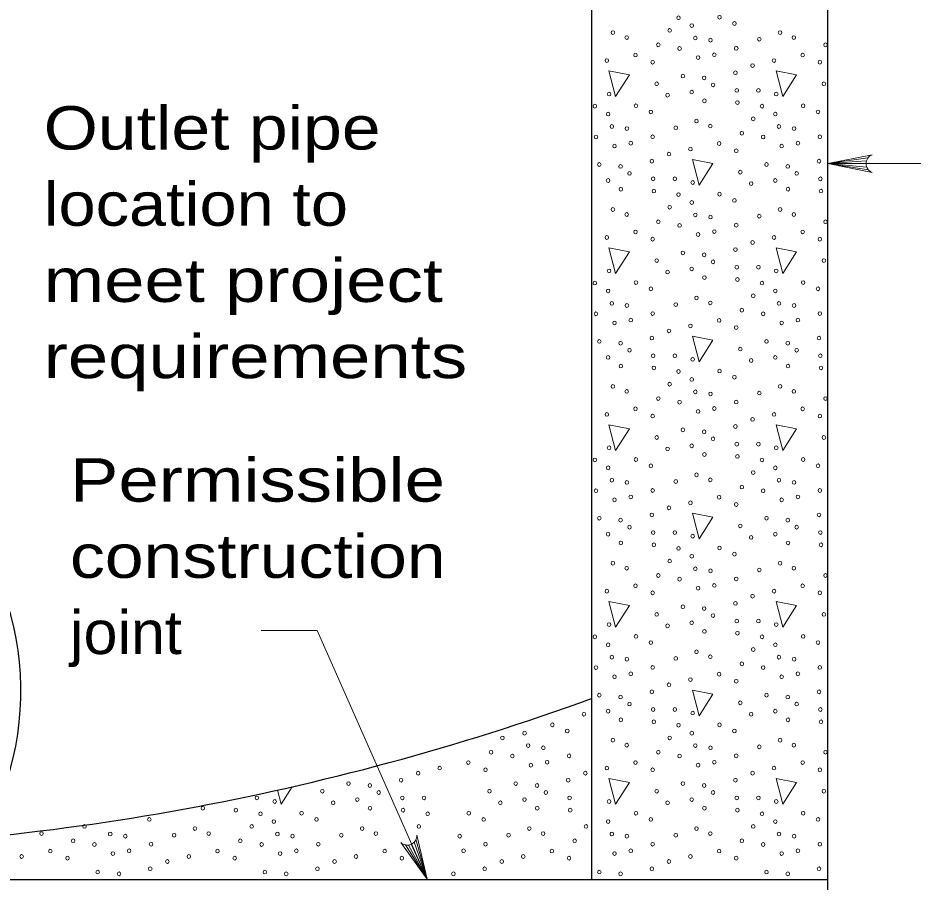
# Model space of a CAD drawing. Extents: x 1352.5 to 1386.5, y 735.9 to 779.9.
# Drawn here: x 1364.306 to 1367.523, y 771.328 to 774.436 of the extents above; entities that cross this region are included whole.
import ezdxf

# ---------------------------------------------------------------- set-up
doc = ezdxf.new("R2010")
doc.units = 0
doc.header["$LTSCALE"] = 0.062
doc.layers.add('1', color=7, linetype='Continuous', lineweight=13)

msp = doc.modelspace()

# ---------------------------------------------------------------- linework, layer by layer
at = {"layer": '1'}
for p, q in [((1367.36042, 773.93233), (1367.21625, 773.91217)), ((1367.35558, 773.92233), (1367.21625, 773.91217)), ((1367.35408, 773.91217), (1367.21625, 773.91217)), ((1367.35658, 773.89917), (1367.21625, 773.91217)), ((1367.36217, 773.88983), (1367.21625, 773.91217)), ((1368.51183, 773.91217), (1367.21625, 773.91217)), ((1365.25217, 771.60883), (1365.29175, 771.67117)), ((1365.23892, 771.659), (1365.25217, 771.60883)), ((1365.73008, 771.47242), (1365.77625, 771.33917)), ((1365.73633, 771.48125), (1365.77625, 771.33917)), ((1365.69833, 771.46217), (1365.77625, 771.33917)), ((1365.70942, 771.46183), (1365.77625, 771.33917)), ((1365.71933, 771.46475), (1365.77625, 771.33917))]:
    msp.add_line(p, q, dxfattribs=at)
at = {"layer": '1', "lineweight": 25}
msp.add_line((1367.21625, 771.33708), (1359.56983, 771.33708), dxfattribs=at)
for points in [[(1366.579, 775.15983), (1366.40908, 775.15983), (1366.36658, 775.11483), (1366.36658, 771.33708)], [(1358.38042, 774.73258), (1359.56983, 774.73258), (1359.56983, 770.66242), (1367.21625, 770.66242), (1367.21625, 774.73258), (1368.40567, 774.73258), (1369.78625, 774.73258)]]:
    msp.add_lwpolyline(points, dxfattribs=at)
at = {"layer": '1'}
for points in [[(1366.42942, 774.24517), (1366.45367, 774.15292), (1366.50308, 774.23083)], [(1367.03017, 774.24517), (1367.05442, 774.15292), (1367.10392, 774.23083)], [(1366.72975, 773.92717), (1366.754, 773.835), (1366.8035, 773.91275)], [(1366.42942, 773.60908), (1366.45367, 773.51692), (1366.50308, 773.59475)], [(1367.03017, 773.60908), (1367.05442, 773.51692), (1367.10392, 773.59475)], [(1366.72975, 773.29108), (1366.754, 773.199), (1366.8035, 773.27675)], [(1366.42942, 772.97308), (1366.45367, 772.88092), (1366.50308, 772.95875)], [(1367.03017, 772.97308), (1367.05442, 772.88092), (1367.10392, 772.95875)], [(1366.72975, 772.65508), (1366.754, 772.56292), (1366.8035, 772.64067)], [(1366.42942, 772.337), (1366.45367, 772.24492), (1366.50308, 772.32275)], [(1367.03017, 772.337), (1367.05442, 772.24492), (1367.10392, 772.32275)], [(1366.72975, 772.01908), (1366.754, 771.92692), (1366.8035, 772.00467)], [(1366.42942, 771.701), (1366.45367, 771.60883), (1366.50308, 771.68667)], [(1367.03017, 771.701), (1367.05442, 771.60883), (1367.10392, 771.68667)]]:
    msp.add_lwpolyline(points, close=True, dxfattribs=at)
for points in [[(1367.3755, 773.88025), (1367.21625, 773.91217), (1367.3755, 773.944)], [(1365.77625, 771.33917), (1365.38183, 772.23358), (1365.18017, 772.23358)], [(1365.7395, 771.49742), (1365.77625, 771.33917), (1365.6815, 771.47108)]]:
    msp.add_lwpolyline(points, dxfattribs=at)
for centre, start, end in [((1367.38838, 773.91218), 112.08782, 247.91395), ((1365.70517, 771.49596), 226.44643, 2.27256)]:
    msp.add_arc(centre, 0.03438, start, end, dxfattribs=at)
for centre in [(1366.67956, 774.43659), (1366.82715, 774.43829), (1366.72737, 774.40824), (1366.88067, 774.41598), (1366.44407, 774.38306), (1366.49353, 774.36504), (1366.64787, 774.39106), (1366.74039, 774.36361), (1366.97018, 774.35905), (1367.04482, 774.38306), (1367.09429, 774.36504), (1366.60707, 774.33928), (1366.79471, 774.35582), (1367.20783, 774.33928), (1366.52512, 774.30234), (1366.68357, 774.32582), (1366.80847, 774.3035), (1366.88717, 774.32661), (1367.12588, 774.30234), (1366.42214, 774.28257), (1366.5868, 774.27658), (1366.75005, 774.29317), (1366.9458, 774.26455), (1367.0229, 774.28257), (1367.18755, 774.27658), (1366.88422, 774.23879), (1366.60141, 774.1993), (1366.69548, 774.22681), (1366.77203, 774.22018), (1367.20217, 774.1993), (1366.72712, 774.16925), (1366.80392, 774.19501), (1366.88908, 774.17524), (1366.96697, 774.17524), (1366.43025, 774.16236), (1366.64036, 774.15807), (1366.77283, 774.13803), (1367.03101, 774.16236), (1366.37918, 774.11858), (1366.52677, 774.12027), (1366.89148, 774.13146), (1366.97994, 774.11858), (1367.12753, 774.12027), (1366.42699, 774.09022), (1366.58029, 774.09796), (1366.94825, 774.07305), (1367.02775, 774.09022), (1367.18104, 774.09796), (1366.44001, 774.04559), (1366.49433, 774.0378), (1366.6698, 774.04104), (1366.74444, 774.06505), (1366.79391, 774.04703), (1367.04077, 774.04559), (1367.09509, 774.0378), (1366.38319, 774.0078), (1366.5868, 774.0086), (1366.90745, 774.02127), (1366.98395, 774.0078), (1367.18755, 774.0086), (1366.44967, 773.97515), (1366.5081, 773.98549), (1366.8255, 773.98432), (1367.05043, 773.97515), (1367.10885, 773.98549), (1366.64542, 773.94653), (1366.72252, 773.96455), (1366.88717, 773.95856), (1366.3951, 773.90879), (1366.58384, 773.92077), (1366.99586, 773.90879), (1367.1846, 773.92077), (1366.47165, 773.90217), (1366.50354, 773.87699), (1366.90179, 773.88129), (1367.07241, 773.90217), (1367.1043, 773.87699), (1366.42674, 773.85123), (1366.5887, 773.85722), (1366.6666, 773.85722), (1367.0275, 773.85123), (1367.18946, 773.85722), (1366.47245, 773.82002), (1366.5911, 773.81344), (1366.73063, 773.84434), (1366.94074, 773.84005), (1367.07321, 773.82002), (1367.19186, 773.81344), (1366.67956, 773.80056), (1366.82715, 773.80226), (1366.64787, 773.75503), (1366.72737, 773.77221), (1366.88067, 773.77995), (1366.44407, 773.74703), (1366.49353, 773.72901), (1366.74039, 773.72758), (1366.79471, 773.71979), (1366.97018, 773.72302), (1367.04482, 773.74703), (1367.09429, 773.72901), (1366.60707, 773.70325), (1366.68357, 773.68979), (1366.88717, 773.69058), (1367.20783, 773.70325), (1366.52512, 773.66631), (1366.75005, 773.65714), (1366.80847, 773.66747), (1367.12588, 773.66631), (1366.42214, 773.64654), (1366.5868, 773.64055), (1366.9458, 773.62852), (1367.0229, 773.64654), (1367.18755, 773.64055), (1366.69548, 773.59078), (1366.88422, 773.60276), (1366.60141, 773.56327), (1366.77203, 773.58415), (1366.80392, 773.55898), (1367.20217, 773.56327), (1366.43025, 773.52633), (1366.72712, 773.53322), (1366.88908, 773.53921), (1366.96697, 773.53921), (1367.03101, 773.52633), (1366.64036, 773.52204), (1366.77283, 773.502), (1366.89148, 773.49543), (1366.37918, 773.48255), (1366.52677, 773.48424), (1366.58029, 773.46193), (1366.97994, 773.48255), (1367.12753, 773.48424), (1367.18104, 773.46193), (1366.42699, 773.45419), (1366.74444, 773.42902), (1366.94825, 773.43702), (1367.02775, 773.45419), (1366.44001, 773.40956), (1366.49433, 773.40177), (1366.6698, 773.40501), (1366.79391, 773.411), (1367.04077, 773.40956), (1367.09509, 773.40177), (1366.38319, 773.37177), (1366.5868, 773.37257), (1366.90745, 773.38524), (1366.98395, 773.37177), (1367.18755, 773.37257), (1366.44967, 773.33912), (1366.5081, 773.34946), (1366.8255, 773.34829), (1367.05043, 773.33912), (1367.10885, 773.34946), (1366.64542, 773.3105), (1366.72252, 773.32852), (1366.88717, 773.32253), (1366.3951, 773.27277), (1366.47165, 773.26614), (1366.58384, 773.28474), (1366.99586, 773.27277), (1367.07241, 773.26614), (1367.1846, 773.28474), (1366.50354, 773.24096), (1366.90179, 773.24526), (1367.1043, 773.24096), (1366.42674, 773.2152), (1366.5887, 773.22119), (1366.6666, 773.22119), (1366.73063, 773.20831), (1366.94074, 773.20402), (1367.0275, 773.2152), (1367.18946, 773.22119), (1366.47245, 773.18399), (1366.5911, 773.17741), (1367.07321, 773.18399), (1367.19186, 773.17741), (1366.67956, 773.16453), (1366.82715, 773.16623), (1366.88067, 773.14392), (1366.44407, 773.111), (1366.64787, 773.119), (1366.72737, 773.13618), (1367.04482, 773.111), (1366.49353, 773.09298), (1366.74039, 773.09155), (1366.79471, 773.08376), (1366.97018, 773.08699), (1367.09429, 773.09298), (1366.60707, 773.06722), (1366.68357, 773.05376), (1366.88717, 773.05455), (1367.20783, 773.06722), (1366.42214, 773.01051), (1366.52512, 773.03028), (1366.75005, 773.02111), (1366.80847, 773.03144), (1367.0229, 773.01051), (1367.12588, 773.03028), (1366.5868, 773.00452), (1366.9458, 772.99249), (1367.18755, 773.00452), (1366.69548, 772.95475), (1366.77203, 772.94812), (1366.88422, 772.96673), (1366.60141, 772.92724), (1366.80392, 772.92295), (1367.20217, 772.92724), (1366.43025, 772.8903), (1366.64036, 772.88601), (1366.72712, 772.89719), (1366.88908, 772.90318), (1366.96697, 772.90318), (1367.03101, 772.8903), (1366.52677, 772.84822), (1366.77283, 772.86597), (1366.89148, 772.8594), (1367.12753, 772.84822), (1366.37918, 772.84652), (1366.42699, 772.81816), (1366.58029, 772.8259), (1366.97994, 772.84652), (1367.02775, 772.81816), (1367.18104, 772.8259), (1366.74444, 772.79299), (1366.94825, 772.80099), (1366.44001, 772.77353), (1366.49433, 772.76574), (1366.6698, 772.76898), (1366.79391, 772.77497), (1367.04077, 772.77353), (1367.09509, 772.76574), (1366.38319, 772.73574), (1366.5868, 772.73654), (1366.90745, 772.74921), (1366.98395, 772.73574), (1367.18755, 772.73654), (1366.44967, 772.70309), (1366.5081, 772.71343), (1366.72252, 772.69249), (1366.8255, 772.71226), (1366.88717, 772.6865), (1367.05043, 772.70309), (1367.10885, 772.71343), (1366.64542, 772.67447), (1366.3951, 772.63674), (1366.47165, 772.63011), (1366.58384, 772.64871), (1366.99586, 772.63674), (1367.07241, 772.63011), (1367.1846, 772.64871), (1366.50354, 772.60493), (1366.90179, 772.60923), (1367.1043, 772.60493), (1366.42674, 772.57917), (1366.5887, 772.58516), (1366.6666, 772.58516), (1366.73063, 772.57228), (1366.94074, 772.56799), (1367.0275, 772.57917), (1367.18946, 772.58516), (1366.47245, 772.54796), (1366.5911, 772.54138), (1366.67956, 772.5285), (1366.82715, 772.5302), (1367.07321, 772.54796), (1367.19186, 772.54138), (1366.72737, 772.50015), (1366.88067, 772.50789), (1366.44407, 772.47497), (1366.64787, 772.48298), (1367.04482, 772.47497), (1366.49353, 772.45695), (1366.60707, 772.43119), (1366.74039, 772.45552), (1366.79471, 772.44773), (1366.97018, 772.45096), (1367.09429, 772.45695), (1367.20783, 772.43119), (1366.68357, 772.41773), (1366.88717, 772.41852), (1366.42214, 772.37448), (1366.52512, 772.39425), (1366.5868, 772.36849), (1366.75005, 772.38508), (1366.80847, 772.39542), (1367.0229, 772.37448), (1367.12588, 772.39425), (1367.18755, 772.36849), (1366.9458, 772.35646), (1366.69548, 772.31872), (1366.77203, 772.3121), (1366.88422, 772.3307), (1366.60141, 772.29121), (1366.80392, 772.28692), (1367.20217, 772.29121), (1366.43025, 772.25427), (1366.64036, 772.24998), (1366.72712, 772.26116), (1366.88908, 772.26715), (1366.96697, 772.26715), (1367.03101, 772.25427), (1366.37918, 772.21049), (1366.52677, 772.21219), (1366.77283, 772.22994), (1366.89148, 772.22337), (1366.97994, 772.21049), (1367.12753, 772.21219), (1366.42699, 772.18213), (1366.58029, 772.18987), (1367.02775, 772.18213), (1367.18104, 772.18987), (1366.74444, 772.15696), (1366.94825, 772.16496), (1366.44001, 772.13751), (1366.49433, 772.12971), (1366.6698, 772.13295), (1366.79391, 772.13894), (1366.90745, 772.11318), (1367.04077, 772.13751), (1367.09509, 772.12971), (1366.38319, 772.09971), (1366.5081, 772.0774), (1366.5868, 772.10051), (1366.8255, 772.07623), (1366.98395, 772.09971), (1367.10885, 772.0774), (1367.18755, 772.10051), (1366.44967, 772.06706), (1366.72252, 772.05646), (1366.88717, 772.05048), (1367.05043, 772.06706), (1366.58384, 772.01268), (1366.64542, 772.03844), (1367.1846, 772.01268), (1366.3951, 772.00071), (1366.47165, 771.99408), (1366.99586, 772.00071), (1367.07241, 771.99408), (1366.50354, 771.9689), (1366.5887, 771.94913), (1366.6666, 771.94913), (1366.90179, 771.9732), (1367.1043, 771.9689), (1367.18946, 771.94913), (1366.33998, 771.93196), (1366.42674, 771.94315), (1366.73063, 771.93625), (1366.94074, 771.93196), (1367.0275, 771.94315), (1366.22639, 771.89417), (1366.47245, 771.91193), (1366.5911, 771.90535), (1366.67956, 771.89247), (1366.82715, 771.89417), (1367.07321, 771.91193), (1367.19186, 771.90535), (1366.12661, 771.86412), (1366.27991, 771.87186), (1366.72737, 771.86412), (1366.88067, 771.87186), (1366.04711, 771.84695), (1366.13963, 771.81949), (1366.44407, 771.83894), (1366.49353, 771.82092), (1366.64787, 771.84695), (1366.74039, 771.81949), (1367.04482, 771.83894), (1367.09429, 771.82092), (1366.00631, 771.79516), (1366.19395, 771.8117), (1366.60707, 771.79516), (1366.79471, 771.8117), (1366.97018, 771.81493), (1367.20783, 771.79516), (1365.92436, 771.75822), (1366.08281, 771.7817), (1366.20772, 771.75939), (1366.28642, 771.78249), (1366.52512, 771.75822), (1366.68357, 771.7817), (1366.80847, 771.75939), (1366.88717, 771.78249), (1367.12588, 771.75822), (1365.82138, 771.73845), (1365.98604, 771.73246), (1366.14929, 771.74905), (1366.42214, 771.73845), (1366.5868, 771.73246), (1366.75005, 771.74905), (1367.0229, 771.73845), (1367.18755, 771.73246), (1365.6827, 771.69467), (1365.74428, 771.72043), (1366.28346, 771.69467), (1366.34504, 771.72043), (1366.88422, 771.69467), (1366.9458, 771.72043), (1365.49397, 771.68269), (1365.57051, 771.67607), (1366.09472, 771.68269), (1366.17127, 771.67607), (1366.69548, 771.68269), (1366.77203, 771.67607), (1365.1647, 771.63112), (1365.3999, 771.65518), (1365.52561, 771.62513), (1365.6024, 771.65089), (1365.68756, 771.63112), (1365.76546, 771.63112), (1366.00066, 771.65518), (1366.12636, 771.62513), (1366.20316, 771.65089), (1366.28832, 771.63112), (1366.60141, 771.65518), (1366.72712, 771.62513), (1366.80392, 771.65089), (1366.88908, 771.63112), (1366.96697, 771.63112), (1367.20217, 771.65518), (1364.97056, 771.59391), (1365.22873, 771.61824), (1365.43885, 771.61395), (1365.57131, 771.59391), (1366.0396, 771.61395), (1366.17207, 771.59391), (1366.43025, 771.61824), (1366.64036, 771.61395), (1366.77283, 771.59391), (1367.03101, 771.61824), (1365.08921, 771.58734), (1365.17767, 771.57446), (1365.32525, 771.57616), (1365.68996, 771.58734), (1365.77843, 771.57446), (1365.92601, 771.57616), (1366.29072, 771.58734), (1366.52677, 771.57616), (1366.89148, 771.58734), (1366.97994, 771.57446), (1367.12753, 771.57616), (1364.54522, 771.52893), (1364.77801, 771.55384), (1365.14598, 771.52893), (1365.22548, 771.5461), (1365.37877, 771.55384), (1365.74674, 771.52893), (1365.97953, 771.55384), (1366.34749, 771.52893), (1366.42699, 771.5461), (1366.58029, 771.55384), (1366.94825, 771.52893), (1367.02775, 771.5461), (1367.18104, 771.55384), (1364.39087, 771.50291), (1364.63774, 771.50148), (1364.86753, 771.49692), (1364.94217, 771.52093), (1364.99163, 771.50291), (1365.23849, 771.50148), (1365.46828, 771.49692), (1365.54293, 771.52093), (1365.59239, 771.50291), (1366.06904, 771.49692), (1366.14369, 771.52093), (1366.19315, 771.50291), (1366.44001, 771.50148), (1366.6698, 771.49692), (1366.74444, 771.52093), (1366.79391, 771.50291), (1367.04077, 771.50148), (1364.50442, 771.47715), (1364.69205, 771.49368), (1364.78452, 771.46448), (1365.10518, 771.47715), (1365.29281, 771.49368), (1365.38528, 771.46448), (1365.89357, 771.49368), (1365.98604, 771.46448), (1366.30669, 771.47715), (1366.49433, 771.49368), (1366.5868, 771.46448), (1366.90745, 771.47715), (1367.09509, 771.49368), (1367.18755, 771.46448), (1364.42246, 771.4402), (1364.58091, 771.46368), (1364.70582, 771.44137), (1365.02322, 771.4402), (1365.18167, 771.46368), (1365.30658, 771.44137), (1365.62398, 771.4402), (1365.90734, 771.44137), (1366.22474, 771.4402), (1366.5081, 771.44137), (1366.8255, 771.4402), (1366.98395, 771.46368), (1367.10885, 771.44137), (1364.31948, 771.42043), (1364.48414, 771.41445), (1364.6474, 771.43104), (1364.84315, 771.40241), (1364.92024, 771.42043), (1365.0849, 771.41445), (1365.24816, 771.43104), (1365.4439, 771.40241), (1365.521, 771.42043), (1365.68566, 771.41445), (1366.04466, 771.40241), (1366.12176, 771.42043), (1366.28642, 771.41445), (1366.44967, 771.43104), (1366.64542, 771.40241), (1366.72252, 771.42043), (1366.88717, 771.41445), (1367.05043, 771.43104), (1364.78157, 771.37665), (1365.38233, 771.37665), (1365.98308, 771.37665), (1366.58384, 771.37665), (1367.1846, 771.37665), (1364.59283, 771.36468), (1364.66938, 771.35805), (1365.19359, 771.36468), (1365.27013, 771.35805), (1365.87089, 771.35805), (1366.3951, 771.36468), (1366.47165, 771.35805), (1366.99586, 771.36468), (1367.07241, 771.35805)]:
    msp.add_ellipse(centre, major_axis=(0, 0.0068), ratio=0.944544, dxfattribs=at)
at = {"layer": '1', "lineweight": 25}
for centre, major_axis, start_param, end_param in [((1363.383, 772.01517), (0, 0.98868), 4.1510277, 8.4127939), ((1363.38303, 772.01517), (0, 0.89948), 4.0735039, 8.490283), ((1363.29509, 781.45697), (0, -10.0114), 0.0103559, 0.3308168)]:
    msp.add_ellipse(centre, major_axis=major_axis, ratio=0.944544, start_param=start_param, end_param=end_param, dxfattribs=at)

# ---------------------------------------------------------------- texts
at = {"layer": '1'}
for s, width, p in [('Outlet pipe', 1.2, (1364.39858, 773.96267)), ('location to', 1.15, (1364.39858, 773.68867)), ('meet project', 1.25, (1364.39858, 773.41467)), ('requirements', 1.25, (1364.39858, 773.14067)), ('Permissible', 1.25, (1364.49317, 772.6965)), ('construction', 1.2, (1364.49317, 772.4225)), ('joint', 1.05, (1364.49317, 772.1485))]:
    msp.add_text(s, height=0.156, dxfattribs=dict(at, width=width)).set_placement(p)

doc.saveas('drawing.dxf')
